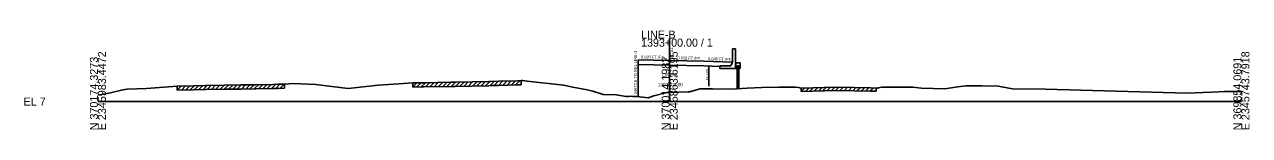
# Model space of a CAD drawing. Extents: x -26 to 2400, y -10 to 9525.
# Drawn here: x -25.7 to 402.8, y 990.3 to 1024.7 of the extents above; entities that cross this region are included whole.
import ezdxf

# ---------------------------------------------------------------- set-up
doc = ezdxf.new("R2010")
doc.units = 0
for name, color, linetype in [('RD_GPK_XS_Cell', 7, 'Continuous'), ('RD_XS_Base', 7, 'Continuous'), ('RD_XS_ExGround', 7, 'Continuous'), ('RD_XS_ExPaveRet', 7, 'Continuous'), ('RD_XS_ExRW', 7, 'Continuous'), ('RD_XS_MatchLine', 7, 'Continuous'), ('RD_XS_MedBWall', 7, 'Continuous'), ('RD_XS_Pave', 7, 'Continuous'), ('RD_XS_PaveShd', 7, 'Continuous'), ('RD_XS_TX_Elev_EX', 7, 'Continuous'), ('RD_XS_TX_Elev_PR', 7, 'Continuous'), ('RD_XS_TX_Slope', 7, 'Continuous'), ('RD_XS_TX_Station', 7, 'Continuous')]:
    doc.layers.add(name, color=color, linetype=linetype)

msp = doc.modelspace()

# ---------------------------------------------------------------- linework, layer by layer
at = {"layer": 'RD_GPK_XS_Cell'}
for p, q in [((200, 1000), (200, 1021.92)), ((0, 1000), (200, 1000)), ((200, 1000), (400, 1000))]:
    msp.add_line(p, q, dxfattribs=at)
at = {"layer": 'RD_XS_Base'}
for p, q in [((189.03, 1012.89), (199.97, 1012.67)), ((199.94, 1012.67), (211.95, 1012.43)), ((211.95, 1012.43), (217.58, 1012.21))]:
    msp.add_line(p, q, dxfattribs=at)
at = {"layer": 'RD_XS_ExGround'}
msp.add_lwpolyline([(0, 1002.26), (1.37, 1002.48), (4.37, 1003.1), (8.75, 1004.05), (9.47, 1004.23), (10.27, 1004.27), (16.94, 1004.52), (27.68, 1005.36), (33.48, 1005.49), (37.57, 1005.6), (44.13, 1005.71), (49.98, 1005.79), (55.28, 1005.88), (61.23, 1005.97), (62.98, 1006.02), (65.31, 1006.07), (68.38, 1006.24), (76.2, 1005.94), (78.04, 1005.71), (87.57, 1004.53), (98.01, 1005.74), (105.21, 1006.16), (110.1, 1006.49), (113.32, 1006.54), (113.96, 1006.55), (123.62, 1006.73), (124.96, 1006.75), (136.76, 1006.97), (137.43, 1006.99), (140.12, 1007.07), (146.75, 1007.26), (148.05, 1007.3), (148.54, 1007.31), (150.15, 1007.14), (162.87, 1005.72), (166.09, 1005.07), (171.12, 1004.06), (173.11, 1003.64), (176.76, 1002.5), (181.3, 1002.3), (184.73, 1001.73), (185.5, 1001.82), (186.44, 1001.84), (187.15, 1001.82), (187.88, 1001.8), (188.51, 1001.76), (189.53, 1001.63), (192.48, 1001.36), (194.42, 1002.01), (198.96, 1003.14), (200, 1003.17), (206.53, 1003.34), (206.95, 1003.41), (210.64, 1004.41), (214.94, 1004.4), (221.82, 1004.32), (227.1, 1004.64), (232.21, 1004.87), (238.17, 1004.99), (244.09, 1005.06), (245.04, 1004.87), (246.02, 1004.67), (254.09, 1004.86), (258.74, 1004.98), (270.3, 1004.75), (272.19, 1004.71), (272.73, 1004.73), (273.09, 1004.74), (274.22, 1004.99), (278.41, 1005.01), (279.75, 1005.03), (285.05, 1005.03), (288.04, 1004.63), (292.13, 1004.51), (296.23, 1004.46), (300.84, 1005.16), (303.57, 1005.52), (309.2, 1005.46), (314.92, 1005.38), (316.16, 1005.12), (319.98, 1004.39), (331.48, 1004.28), (380.97, 1002.9), (386.48, 1003.13), (389.6, 1003.23), (392.17, 1003.42), (394, 1003.48), (400, 1003.55)], dxfattribs=at)
at = {"layer": 'RD_XS_ExPaveRet'}
for p, q in [((138.6, 1005.58), (140.08, 1007.06)), ((140.1, 1005.63), (141.58, 1007.11)), ((141.6, 1005.67), (143.08, 1007.15)), ((143.1, 1005.72), (144.58, 1007.2)), ((144.6, 1005.76), (146.08, 1007.24)), ((146.1, 1005.8), (147.58, 1007.28)), ((148.05, 1007.3), (148.05, 1005.86)), ((27.68, 1003.93), (29.15, 1005.4)), ((27.68, 1003.93), (27.68, 1005.36)), ((27.68, 1003.93), (33.48, 1004.06)), ((29.18, 1003.96), (30.65, 1005.43)), ((30.68, 1003.99), (32.15, 1005.46)), ((32.18, 1004.03), (33.65, 1005.5)), ((33.48, 1004.06), (37.57, 1004.16)), ((33.68, 1004.06), (35.16, 1005.54)), ((35.18, 1004.1), (36.66, 1005.58)), ((36.68, 1004.14), (38.15, 1005.61)), ((37.57, 1004.16), (44.13, 1004.27)), ((38.18, 1004.17), (39.64, 1005.64)), ((39.68, 1004.2), (41.14, 1005.66)), ((41.18, 1004.22), (42.64, 1005.69)), ((42.68, 1004.25), (44.14, 1005.71)), ((44.13, 1004.27), (49.98, 1004.36)), ((44.18, 1004.27), (45.64, 1005.73)), ((45.68, 1004.29), (47.14, 1005.75)), ((47.18, 1004.32), (48.64, 1005.77)), ((48.68, 1004.34), (50.14, 1005.79)), ((49.98, 1004.36), (55.28, 1004.44)), ((50.18, 1004.36), (51.64, 1005.82)), ((51.68, 1004.38), (53.14, 1005.84)), ((53.18, 1004.41), (54.64, 1005.87)), ((54.68, 1004.43), (56.14, 1005.89)), ((55.28, 1004.44), (61.23, 1004.54)), ((56.18, 1004.45), (57.64, 1005.91)), ((57.68, 1004.48), (59.14, 1005.94)), ((59.18, 1004.5), (60.64, 1005.96)), ((60.68, 1004.53), (62.15, 1006)), ((61.23, 1004.54), (62.98, 1004.58)), ((62.18, 1004.56), (63.65, 1006.03)), ((62.98, 1004.58), (65.31, 1004.63)), ((63.68, 1004.6), (65.15, 1006.07)), ((65.31, 1006.07), (65.31, 1004.63)), ((110.1, 1005.05), (111.56, 1006.51)), ((110.1, 1005.05), (110.1, 1006.49)), ((110.1, 1005.05), (113.32, 1005.11)), ((111.6, 1005.08), (113.06, 1006.54)), ((113.1, 1005.1), (114.56, 1006.56)), ((113.32, 1005.11), (113.96, 1005.11)), ((113.96, 1005.11), (123.62, 1005.29)), ((114.6, 1005.12), (116.06, 1006.59)), ((116.1, 1005.15), (117.56, 1006.62)), ((117.6, 1005.18), (119.06, 1006.64)), ((119.1, 1005.21), (120.56, 1006.67)), ((120.6, 1005.23), (122.06, 1006.7)), ((122.1, 1005.26), (123.56, 1006.72)), ((123.6, 1005.29), (125.06, 1006.75)), ((123.62, 1005.29), (124.96, 1005.31)), ((124.96, 1005.31), (136.76, 1005.54)), ((125.1, 1005.31), (126.56, 1006.78)), ((126.6, 1005.34), (128.06, 1006.81)), ((128.1, 1005.37), (129.56, 1006.84)), ((129.6, 1005.4), (131.06, 1006.87)), ((131.1, 1005.43), (132.56, 1006.89)), ((132.6, 1005.46), (134.06, 1006.92)), ((134.1, 1005.49), (135.56, 1006.95)), ((135.6, 1005.52), (137.06, 1006.98)), ((136.76, 1005.54), (137.43, 1005.55)), ((137.1, 1005.54), (138.58, 1007.02)), ((137.43, 1005.55), (140.12, 1005.63)), ((140.12, 1005.63), (146.75, 1005.82)), ((146.75, 1005.82), (148.05, 1005.86)), ((246.02, 1003.53), (247.2, 1004.7)), ((246.02, 1003.53), (246.02, 1004.67)), ((246.02, 1003.53), (254.09, 1003.72)), ((247.52, 1003.56), (248.7, 1004.73)), ((249.02, 1003.6), (250.2, 1004.77)), ((250.52, 1003.63), (251.7, 1004.81)), ((252.02, 1003.67), (253.2, 1004.84)), ((253.52, 1003.71), (254.7, 1004.88)), ((254.09, 1003.72), (258.74, 1003.83)), ((255.02, 1003.74), (256.2, 1004.91)), ((256.52, 1003.78), (257.7, 1004.95)), ((258.02, 1003.82), (259.18, 1004.97)), ((258.74, 1003.83), (270.3, 1003.61)), ((259.52, 1003.82), (260.65, 1004.94)), ((261.02, 1003.79), (262.15, 1004.91)), ((262.52, 1003.76), (263.65, 1004.88)), ((264.02, 1003.73), (265.15, 1004.85)), ((265.52, 1003.7), (266.65, 1004.82)), ((267.02, 1003.67), (268.15, 1004.79)), ((268.52, 1003.64), (269.65, 1004.76)), ((270.02, 1003.61), (271.15, 1004.73)), ((270.3, 1003.61), (272.19, 1003.57)), ((272.19, 1004.71), (272.19, 1003.57))]:
    msp.add_line(p, q, dxfattribs=at)
at = {"layer": 'RD_XS_ExRW'}
msp.add_line((213.67, 1005.4), (213.67, 1012.4), dxfattribs=at)
at = {"layer": 'RD_XS_MatchLine'}
msp.add_line((189.03, 1014.53), (189.03, 1001.7), dxfattribs=at)
at = {"layer": 'RD_XS_MedBWall'}
for p, q in [((222, 1013.67), (222, 1018.34)), ((222, 1018.34), (223, 1018.34)), ((222, 1013.67), (222, 1018.34)), ((222, 1018.34), (223, 1018.34)), ((223, 1018.34), (223, 1013.67)), ((217.58, 1011.5), (217.58, 1012.5)), ((217.58, 1012.5), (221.37, 1012.5)), ((223.08, 1011.5), (217.58, 1011.5)), ((221.37, 1012.5), (221.86, 1013.5)), ((221.86, 1013.5), (222, 1013.67)), ((223, 1013.67), (223.08, 1013.67)), ((223.08, 1013.67), (223.08, 1011.5)), ((223.08, 1013.5), (223.15, 1013.5)), ((223.15, 1013.5), (224.65, 1013.5)), ((223.15, 1011.5), (223.15, 1013.5)), ((223.65, 1011.5), (223.15, 1011.5)), ((224.15, 1012.5), (223.65, 1012.5)), ((223.65, 1012.5), (223.65, 1011.5)), ((223.65, 1011.5), (223.65, 1004.43)), ((224.15, 1011.5), (224.15, 1012.5)), ((224.65, 1011.5), (224.15, 1011.5)), ((224.15, 1011.5), (224.15, 1004.46)), ((224.65, 1013.5), (224.65, 1011.5))]:
    msp.add_line(p, q, dxfattribs=at)
at = {"layer": 'RD_XS_Pave'}
for p, q in [((189.03, 1014.53), (200, 1014.31)), ((200, 1014.31), (212, 1014.07))]:
    msp.add_line(p, q, dxfattribs=at)
at = {"layer": 'RD_XS_PaveShd'}
msp.add_line((212, 1014.07), (222, 1013.67), dxfattribs=at)

# ---------------------------------------------------------------- texts
at = {"layer": 'RD_GPK_XS_Cell'}
for s, p in [('LINE-B', (190, 1021.92)), ('1393+00.00 / 1', (190, 1019.12)), ('EL 7', (-26, 998.6))]:
    msp.add_text(s, height=2.8, dxfattribs=at).set_placement(p)
for s, p in [('E 2345983.4472', (2.8, 990)), ('E 2345863.6195', (202.8, 990)), ('E 2345743.7918', (402.8, 990)), ('N 370174.3273', (0, 990)), ('N 370014.1982', (200, 990)), ('N 369854.0691', (400, 990))]:
    msp.add_text(s, height=2.8, rotation=90, dxfattribs=at).set_placement(p)
at = {"layer": 'RD_XS_ExRW'}
msp.add_text('EX. R/W ', height=0.75, rotation=90, dxfattribs=at).set_placement((213.41, 1007.43))
at = {"layer": 'RD_XS_TX_Elev_EX'}
msp.add_text('10.17', height=1, rotation=90, dxfattribs=at).set_placement((200.5, 1003.17))
at = {"layer": 'RD_XS_TX_Elev_PR'}
msp.add_text(' 21.31', height=1.2, rotation=90, dxfattribs=at).set_placement((201.2, 1014.31))
at = {"layer": 'RD_XS_TX_Slope'}
for s, rotation, p in [('0.020 FT./FT.', 358.8542, (189.93, 1015.07)), ('0.020 FT./FT.', 358.8542, (202.69, 1014.7)), ('0.040 FT./FT.', 357.7094, (213.42, 1014.49))]:
    msp.add_text(s, height=1, rotation=rotation, dxfattribs=at).set_placement(p)
at = {"layer": 'RD_XS_TX_Station'}
msp.add_text('MATCH TO REL LINE-3', height=1, rotation=90, dxfattribs=at).set_placement((188.54, 1002.74))
for s, p in [('LINE-B', (197.43, 1008.61)), ('1393+00.00', (195.82, 1005.31))]:
    msp.add_text(s, height=1.2, dxfattribs=at).set_placement(p)

doc.saveas('drawing.dxf')
